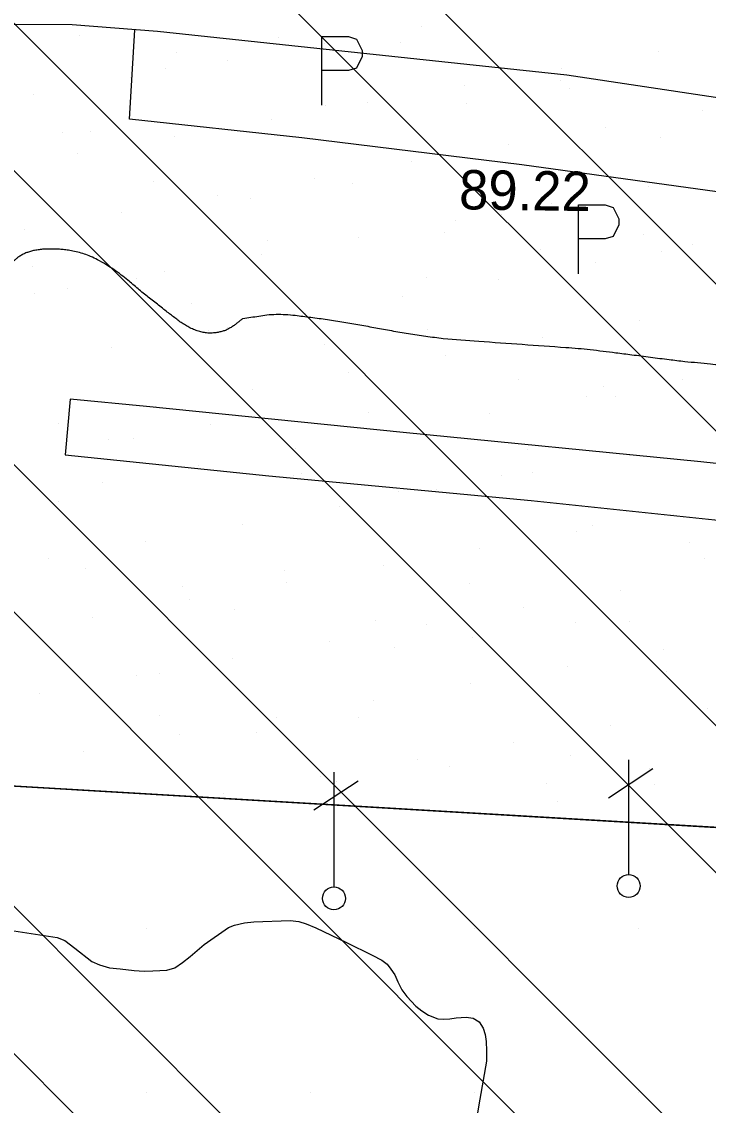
# Model space of a CAD drawing. Extents: x 417995 to 421451, y 4454518 to 4458015.
# Drawn here: x 420558.9 to 420663.7, y 4455397.6 to 4455562.9 of the extents above; entities that cross this region are included whole.
import ezdxf

# ---------------------------------------------------------------- set-up
doc = ezdxf.new("R2010")
doc.units = 0
for name, color, linetype in [('ADAKENARI', 7, 'Continuous'), ('B_Betonzemin', 7, 'Continuous'), ('Egri_1m', 7, 'Continuous'), ('PL_AYA_FUAR', 7, 'Continuous'), ('PL_KAMU_HİZMET_ALANI', 7, 'Continuous'), ('S_Otopark', 7, 'Continuous'), ('S_Telefon_Diregi', 7, 'Continuous'), ('Sinir_itirazli_Mulkiyet', 7, 'Continuous'), ('SN_TR_SIVILASMA', 7, 'Continuous'), ('TRFAT_KHA', 7, 'Continuous'), ('TRFAT_PARKALANI', 7, 'Continuous'), ('Y_Kot_Noktasi', 7, 'Continuous'), ('Yol_Kaldirim_kenari_bordurtasi', 7, 'Continuous'), ('Yol_Sose', 7, 'Continuous')]:
    doc.layers.add(name, color=color, linetype=linetype)

msp = doc.modelspace()

# ---------------------------------------------------------------- linework, layer by layer
at = {"layer": 'ADAKENARI'}
msp.add_line((420549.3, 4455446.81), (420710.4, 4455437.34), dxfattribs=at)
at = {"layer": 'B_Betonzemin'}
msp.add_lwpolyline([(420687.89, 4455493.02), (420662.57, 4455495.76), (420617.14, 4455500.26), (420577.96, 4455504.2), (420566.34, 4455505.34), (420565.56, 4455496.82), (420596.64, 4455493.66), (420636.68, 4455489.9), (420679.17, 4455485.42), (420687.13, 4455484.63)], dxfattribs=at)
at = {"layer": 'Egri_1m'}
for points in [[(420592.68, 4455517.63), (420592.27, 4455517.31), (420591.85, 4455516.98), (420591.44, 4455516.66), (420591.02, 4455516.34), (420590.52, 4455516.07), (420590.02, 4455515.82), (420589.47, 4455515.66), (420588.9, 4455515.51), (420588.2, 4455515.43), (420587.51, 4455515.39), (420586.82, 4455515.49), (420586.11, 4455515.63), (420585.36, 4455515.9), (420584.62, 4455516.2), (420583.93, 4455516.6), (420583.26, 4455517.02), (420582.61, 4455517.51), (420581.96, 4455518), (420581.32, 4455518.49), (420580.62, 4455519.03), (420579.84, 4455519.65), (420579.05, 4455520.26), (420578.26, 4455520.88), (420577.48, 4455521.51), (420576.69, 4455522.17), (420575.9, 4455522.83), (420575.12, 4455523.5), (420574.13, 4455524.26), (420572.98, 4455525.1), (420571.77, 4455525.86), (420570.52, 4455526.59), (420569.46, 4455527.09), (420568.51, 4455527.47), (420567.52, 4455527.75), (420566.52, 4455527.97), (420565.68, 4455528.1), (420564.91, 4455528.18), (420564.13, 4455528.22), (420563.35, 4455528.23), (420562.64, 4455528.21), (420561.95, 4455528.17), (420561.26, 4455528.07), (420560.57, 4455527.95), (420559.99, 4455527.77), (420559.43, 4455527.57), (420558.91, 4455527.28), (420558.4, 4455526.98), (420558.07, 4455526.7), (420557.75, 4455526.43)], [(420592.68, 4455517.63), (420593.9, 4455517.82), (420595.12, 4455518.01), (420596.33, 4455518.2), (420597.76, 4455518.27), (420599.21, 4455518.25), (420600.66, 4455518.12), (420603.05, 4455517.82), (420605.58, 4455517.48), (420608.11, 4455517.09), (420610.54, 4455516.66), (420612.95, 4455516.22), (420615.36, 4455515.78), (420617.95, 4455515.36), (420620.6, 4455514.95), (420623.27, 4455514.6), (420628.67, 4455514.17), (420635.32, 4455513.7), (420641.97, 4455513.22), (420645.68, 4455512.9), (420647.64, 4455512.66), (420649.59, 4455512.42), (420652.04, 4455512.11), (420654.88, 4455511.74), (420657.71, 4455511.38), (420660.11, 4455511.1), (420662.07, 4455510.9), (420664.03, 4455510.71), (420665.57, 4455510.55), (420666.55, 4455510.41), (420667.53, 4455510.25), (420668.69, 4455510.03), (420670.16, 4455509.72), (420671.61, 4455509.31), (420672.93, 4455508.87), (420673.96, 4455508.4), (420674.99, 4455507.92), (420676.53, 4455507.29), (420679.6, 4455506.24), (420682.67, 4455505.19), (420685.44, 4455504.22), (420686.9, 4455503.64), (420688.34, 4455503.02), (420689.76, 4455502.37), (420691.11, 4455501.69), (420692.41, 4455500.93), (420693.61, 4455500.16), (420693.9, 4455499.94), (420694.2, 4455499.71), (420694.49, 4455499.49)]]:
    msp.add_spline(points, degree=3, dxfattribs=at)
at = {"layer": 'PL_AYA_FUAR'}
msp.add_lwpolyline([(420787.06, 4455778.4), (420884.04, 4455668.02), (420888.93, 4455658.72), (420890.16, 4455653.06), (420890.46, 4455645.54), (420886.58, 4455581.52), (420884.98, 4455552.19), (420718.56, 4455563.04), (420710.4, 4455437.34), (420549.3, 4455446.81)], dxfattribs=at)
at = {"layer": 'PL_KAMU_HİZMET_ALANI'}
msp.add_lwpolyline([(420705.27, 4455005.33), (420707.29, 4455006.2), (420751.48, 4455032.99), (420769.07, 4455051.2), (420804.89, 4455072.7), (420840.78, 4455094.99), (420847.65, 4455100.22), (420853.39, 4455106.67), (420857.79, 4455114.1), (420861.99, 4455130.83), (420878.18, 4455427.47), (420710.4, 4455437.34), (420545.42, 4455447.04), (420544.85, 4455437.97), (420540.37, 4455429.06), (420482.57, 4455314.58), (420453.85, 4455245.63), (420452.99, 4455236.3), (420611.77, 4455234.39), (420610.24, 4455191.26), (420608.01, 4455006.36)], dxfattribs=at)
at = {"layer": 'S_Otopark'}
for points in [[(420604.73, 4455560.65), (420608.83, 4455560.65)], [(420604.73, 4455550.15), (420604.73, 4455560.65)], [(420608.83, 4455560.65), (420610.05, 4455560.23), (420610.89, 4455558.52), (420610.89, 4455557.61), (420610.05, 4455555.82), (420608.83, 4455555.47)], [(420608.83, 4455555.47), (420604.73, 4455555.47)], [(420643.89, 4455534.97), (420647.99, 4455534.97)], [(420643.89, 4455524.47), (420643.89, 4455534.97)], [(420647.99, 4455534.97), (420649.21, 4455534.55), (420650.05, 4455532.83), (420650.05, 4455531.92), (420649.21, 4455530.14), (420647.99, 4455529.79)], [(420647.99, 4455529.79), (420643.89, 4455529.79)]]:
    msp.add_lwpolyline(points, dxfattribs=at)
at = {"layer": 'S_Telefon_Diregi'}
for p, q in [((420651.58, 4455432.83), (420651.58, 4455450.33)), ((420606.62, 4455430.94), (420606.62, 4455448.44)), ((420648.47, 4455444.55), (420655.22, 4455449)), ((420603.5, 4455442.67), (420610.26, 4455447.11))]:
    msp.add_line(p, q, dxfattribs=at)
for centre in [(420651.55, 4455431.08), (420606.58, 4455429.19)]:
    msp.add_circle(centre, 1.75, dxfattribs=at)
at = {"layer": 'Sinir_itirazli_Mulkiyet'}
msp.add_lwpolyline([(420557.73, 4455424.26), (420564.35, 4455423.23), (420565.55, 4455422.74), (420567.06, 4455421.57), (420569.65, 4455419.54), (420570.79, 4455419.07), (420572.33, 4455418.62), (420573.98, 4455418.43), (420576.1, 4455418.18), (420577.63, 4455418.08), (420578.93, 4455418.13), (420581.1, 4455418.25), (420582.31, 4455418.6), (420583.5, 4455419.41), (420584.66, 4455420.34), (420586.79, 4455422.17), (420590.48, 4455424.77), (420591.4, 4455425.12), (420592.96, 4455425.46), (420594.34, 4455425.63), (420599.89, 4455425.82), (420601.22, 4455425.64), (420602.35, 4455425.33), (420603.81, 4455424.68), (420608.52, 4455422.44), (420612.42, 4455420.51), (420613.89, 4455419.76), (420614.7, 4455419.14), (420615.25, 4455418.39), (420615.86, 4455417.55), (420616.31, 4455416.45), (420616.92, 4455415.22), (420617.71, 4455414.21), (420619.09, 4455412.77), (420619.99, 4455412.04), (420621, 4455411.37), (420622.42, 4455410.82), (420623.34, 4455410.78), (420624.26, 4455410.84), (420625.25, 4455410.98), (420626.74, 4455411.06), (420627.81, 4455410.92), (420628.72, 4455410.34), (420629.36, 4455409.37), (420629.65, 4455408.44), (420629.83, 4455407.37), (420629.87, 4455405.93), (420629.84, 4455404.34), (420628.82, 4455398.57), (420627.82, 4455392.54)], dxfattribs=at)
at = {"layer": 'SN_TR_SIVILASMA'}
for p, q in [((421187.51, 4455000.24), (420079.94, 4456107.81)), ((421164.82, 4455000.48), (420095.66, 4456069.64)), ((421119.44, 4455000.96), (420129.33, 4455991.06)), ((421096.75, 4455001.2), (420145.11, 4455952.83)), ((421051.37, 4455001.68), (420175.05, 4455878)), ((421028.68, 4455001.92), (420190.02, 4455840.58)), ((420983.3, 4455002.39), (420204.76, 4455780.94)), ((420960.61, 4455002.63), (420211.17, 4455752.07))]:
    msp.add_line(p, q, dxfattribs=at)
at = {"layer": 'TRFAT_KHA'}
for p, q in [((420577.99, 4455424.6), (420577.99, 4455424.6)), ((420602.99, 4455424.6), (420602.99, 4455424.6)), ((420627.99, 4455424.6), (420627.99, 4455424.6)), ((420652.99, 4455424.6), (420652.99, 4455424.6)), ((420577.99, 4455399.6), (420577.99, 4455399.6)), ((420602.99, 4455399.6), (420602.99, 4455399.6)), ((420627.99, 4455399.6), (420627.99, 4455399.6)), ((420652.99, 4455399.6), (420652.99, 4455399.6))]:
    msp.add_line(p, q, dxfattribs=at)
at = {"layer": 'TRFAT_PARKALANI'}
for p, q in [((420619.87, 4455562.17), (420619.87, 4455562.17)), ((420567.78, 4455560.82), (420567.78, 4455560.82)), ((420598.19, 4455560.54), (420598.19, 4455560.54)), ((420605.1, 4455559.56), (420605.1, 4455559.56)), ((420616.77, 4455559.69), (420616.77, 4455559.69)), ((420582.55, 4455558.22), (420582.55, 4455558.22)), ((420590.33, 4455556.96), (420590.33, 4455556.96)), ((420656.08, 4455558.4), (420656.08, 4455558.4)), ((420580.93, 4455555.73), (420580.93, 4455555.73)), ((420641.3, 4455555.79), (420641.3, 4455555.79)), ((420575.56, 4455554.35), (420575.56, 4455554.35)), ((420641.11, 4455554.01), (420641.11, 4455554.01)), ((420612.1, 4455553.01), (420612.1, 4455553.01)), ((420626.53, 4455553.19), (420626.53, 4455553.19)), ((420642.51, 4455552.72), (420642.51, 4455552.72)), ((420560.78, 4455551.75), (420560.78, 4455551.75)), ((420611.76, 4455550.58), (420611.76, 4455550.58)), ((420626.87, 4455550.4), (420626.87, 4455550.4)), ((420605.28, 4455550.05), (420605.28, 4455550.05)), ((420662.74, 4455549.42), (420662.74, 4455549.42)), ((420596.99, 4455547.98), (420596.99, 4455547.98)), ((420565.18, 4455546.05), (420565.18, 4455546.05)), ((420569.44, 4455546.08), (420569.44, 4455546.08)), ((420582.22, 4455545.37), (420582.22, 4455545.37)), ((420647.97, 4455546.81), (420647.97, 4455546.81)), ((420633.19, 4455544.21), (420633.19, 4455544.21)), ((420656.41, 4455545.19), (420656.41, 4455545.19)), ((420567.44, 4455542.77), (420567.44, 4455542.77)), ((420618.42, 4455541.6), (420618.42, 4455541.6)), ((420603.65, 4455539), (420603.65, 4455539)), ((420579.08, 4455538.52), (420579.08, 4455538.52)), ((420609.49, 4455538.23), (420609.49, 4455538.23)), ((420654.63, 4455537.83), (420654.63, 4455537.83)), ((420588.88, 4455536.39), (420588.88, 4455536.39)), ((420593.85, 4455535.92), (420593.85, 4455535.92)), ((420639.85, 4455535.23), (420639.85, 4455535.23)), ((420574.1, 4455533.79), (420574.1, 4455533.79)), ((420625.08, 4455532.62), (420625.08, 4455532.62)), ((420632.22, 4455533.49), (420632.22, 4455533.49)), ((420559.33, 4455531.18), (420559.33, 4455531.18)), ((420623.4, 4455530.71), (420623.4, 4455530.71)), ((420596.38, 4455529.53), (420596.38, 4455529.53)), ((420610.31, 4455530.02), (420610.31, 4455530.02)), ((420653.81, 4455530.42), (420653.81, 4455530.42)), ((420661.29, 4455528.85), (420661.29, 4455528.85)), ((420595.54, 4455527.41), (420595.54, 4455527.41)), ((420638.17, 4455528.1), (420638.17, 4455528.1)), ((420656.57, 4455527.81), (420656.57, 4455527.81)), ((420560.55, 4455525.57), (420560.55, 4455525.57)), ((420646.51, 4455526.25), (420646.51, 4455526.25)), ((420580.77, 4455524.81), (420580.77, 4455524.81)), ((420576.48, 4455523.75), (420576.48, 4455523.75)), ((420620.73, 4455523.85), (420620.73, 4455523.85)), ((420631.74, 4455523.64), (420631.74, 4455523.64)), ((420560.84, 4455521.43), (420560.84, 4455521.43)), ((420565.99, 4455522.2), (420565.99, 4455522.2)), ((420616.97, 4455521.04), (420616.97, 4455521.04)), ((420584.89, 4455519.89), (420584.89, 4455519.89)), ((420602.2, 4455518.43), (420602.2, 4455518.43)), ((420587.43, 4455515.83), (420587.43, 4455515.83)), ((420590.38, 4455516.22), (420590.38, 4455516.22)), ((420620.79, 4455515.93), (420620.79, 4455515.93)), ((420653.17, 4455517.27), (420653.17, 4455517.27)), ((420638.4, 4455514.66), (420638.4, 4455514.66)), ((420572.65, 4455513.22), (420572.65, 4455513.22)), ((420605.15, 4455513.61), (420605.15, 4455513.61)), ((420623.63, 4455512.06), (420623.63, 4455512.06)), ((420608.86, 4455509.45), (420608.86, 4455509.45)), ((420634.7, 4455508.4), (420634.7, 4455508.4)), ((420659.84, 4455508.29), (420659.84, 4455508.29)), ((420594.09, 4455506.85), (420594.09, 4455506.85)), ((420647.67, 4455507.3), (420647.67, 4455507.3)), ((420649.47, 4455505.8), (420649.47, 4455505.8)), ((420579.31, 4455504.24), (420579.31, 4455504.24)), ((420645.06, 4455505.68), (420645.06, 4455505.68)), ((420611.84, 4455503.34), (420611.84, 4455503.34)), ((420630.29, 4455503.08), (420630.29, 4455503.08)), ((420564.54, 4455501.64), (420564.54, 4455501.64)), ((420587.78, 4455501.45), (420587.78, 4455501.45)), ((420572.13, 4455499.13), (420572.13, 4455499.13)), ((420576, 4455499.37), (420576, 4455499.37)), ((420615.52, 4455500.47), (420615.52, 4455500.47)), ((420600.75, 4455497.87), (420600.75, 4455497.87)), ((420636.18, 4455497.66), (420636.18, 4455497.66)), ((420651.72, 4455496.7), (420651.72, 4455496.7)), ((420585.97, 4455495.26), (420585.97, 4455495.26)), ((420571.2, 4455492.66), (420571.2, 4455492.66)), ((420600.35, 4455493.69), (420600.35, 4455493.69)), ((420601.68, 4455493.92), (420601.68, 4455493.92)), ((420632.09, 4455493.63), (420632.09, 4455493.63)), ((420636.95, 4455494.1), (420636.95, 4455494.1)), ((420616.45, 4455491.31), (420616.45, 4455491.31)), ((420622.18, 4455491.49), (420622.18, 4455491.49)), ((420564.51, 4455489.73), (420564.51, 4455489.73)), ((420607.41, 4455488.89), (420607.41, 4455488.89)), ((420658.38, 4455487.72), (420658.38, 4455487.72)), ((420592.64, 4455486.28), (420592.64, 4455486.28)), ((420646, 4455486.1), (420646, 4455486.1)), ((420643.61, 4455485.12), (420643.61, 4455485.12)), ((420577.86, 4455483.68), (420577.86, 4455483.68)), ((420660.77, 4455483.5), (420660.77, 4455483.5)), ((420563.09, 4455481.07), (420563.09, 4455481.07)), ((420628.84, 4455482.51), (420628.84, 4455482.51)), ((420663.13, 4455481.1), (420663.13, 4455481.1)), ((420568.66, 4455479.43), (420568.66, 4455479.43)), ((420614.07, 4455479.91), (420614.07, 4455479.91)), ((420599.07, 4455479.15), (420599.07, 4455479.15)), ((420583.43, 4455476.83), (420583.43, 4455476.83)), ((420599.3, 4455477.3), (420599.3, 4455477.3)), ((420627.29, 4455477.14), (420627.29, 4455477.14)), ((420650.27, 4455476.14), (420650.27, 4455476.14)), ((420584.52, 4455474.7), (420584.52, 4455474.7)), ((420591.45, 4455473.18), (420591.45, 4455473.18)), ((420635.5, 4455473.53), (420635.5, 4455473.53)), ((420569.75, 4455472.09), (420569.75, 4455472.09)), ((420612.98, 4455471.62), (420612.98, 4455471.62)), ((420643.39, 4455471.33), (420643.39, 4455471.33)), ((420651.64, 4455471.46), (420651.64, 4455471.46)), ((420620.73, 4455470.93), (420620.73, 4455470.93)), ((420605.96, 4455468.32), (420605.96, 4455468.32)), ((420627.75, 4455469.01), (420627.75, 4455469.01)), ((420615.8, 4455467.5), (420615.8, 4455467.5)), ((420656.93, 4455467.16), (420656.93, 4455467.16)), ((420566.06, 4455464.66), (420566.06, 4455464.66)), ((420591.18, 4455465.72), (420591.18, 4455465.72)), ((420642.16, 4455464.55), (420642.16, 4455464.55)), ((420576.41, 4455463.11), (420576.41, 4455463.11)), ((420579.96, 4455463.54), (420579.96, 4455463.54)), ((420657.29, 4455463.8), (420657.29, 4455463.8)), ((420627.39, 4455461.95), (420627.39, 4455461.95)), ((420561.64, 4455460.51), (420561.64, 4455460.51)), ((420612.62, 4455459.34), (420612.62, 4455459.34)), ((420663.59, 4455458.18), (420663.59, 4455458.18)), ((420579.96, 4455457.13), (420579.96, 4455457.13)), ((420597.84, 4455456.74), (420597.84, 4455456.74)), ((420610.37, 4455456.85), (420610.37, 4455456.85)), ((420594.73, 4455454.53), (420594.73, 4455454.53)), ((420648.82, 4455455.57), (420648.82, 4455455.57)), ((420583.07, 4455454.13), (420583.07, 4455454.13)), ((420634.05, 4455452.97), (420634.05, 4455452.97)), ((420568.3, 4455451.53), (420568.3, 4455451.53)), ((420619.28, 4455450.36), (420619.28, 4455450.36)), ((420642.74, 4455450.94), (420642.74, 4455450.94)), ((420624.28, 4455449.32), (420624.28, 4455449.32)), ((420654.69, 4455449.03), (420654.69, 4455449.03)), ((420604.51, 4455447.76), (420604.51, 4455447.76)), ((420606.91, 4455446.98), (420606.91, 4455446.98)), ((420639.05, 4455446.71), (420639.05, 4455446.71)), ((420655.48, 4455446.59), (420655.48, 4455446.59)), ((420589.73, 4455445.15), (420589.73, 4455445.15)), ((420640.71, 4455443.99), (420640.71, 4455443.99))]:
    msp.add_line(p, q, dxfattribs=at)
at = {"layer": 'Yol_Kaldirim_kenari_bordurtasi'}
msp.add_lwpolyline([(420700.89, 4455532.57), (420676.07, 4455535.43), (420635.23, 4455541.07), (420601.69, 4455545.21), (420575.38, 4455548.03), (420576.18, 4455561.67)], dxfattribs=at)
at = {"layer": 'Yol_Sose'}
msp.add_lwpolyline([(420700.79, 4455529.7), (420701.04, 4455536.78), (420700.91, 4455542.18), (420700.42, 4455544.3), (420699.73, 4455545.34), (420698.94, 4455546.03), (420698.01, 4455546.51), (420696.81, 4455546.71), (420687.48, 4455547.93), (420642.14, 4455554.75), (420579.64, 4455561.39), (420566.63, 4455562.44), (420558.05, 4455562.48), (420556.15, 4455562.16), (420554.24, 4455561.16), (420552.92, 4455559.95), (420551.6, 4455557.85), (420550.39, 4455554.27), (420548.7, 4455543.4)], dxfattribs=at)

# ---------------------------------------------------------------- texts
at = {"layer": 'Y_Kot_Noktasi'}
msp.add_text('89.22', height=6, rotation=359.1542, dxfattribs=at).set_placement((420625.65, 4455534.3))

doc.saveas('drawing.dxf')
